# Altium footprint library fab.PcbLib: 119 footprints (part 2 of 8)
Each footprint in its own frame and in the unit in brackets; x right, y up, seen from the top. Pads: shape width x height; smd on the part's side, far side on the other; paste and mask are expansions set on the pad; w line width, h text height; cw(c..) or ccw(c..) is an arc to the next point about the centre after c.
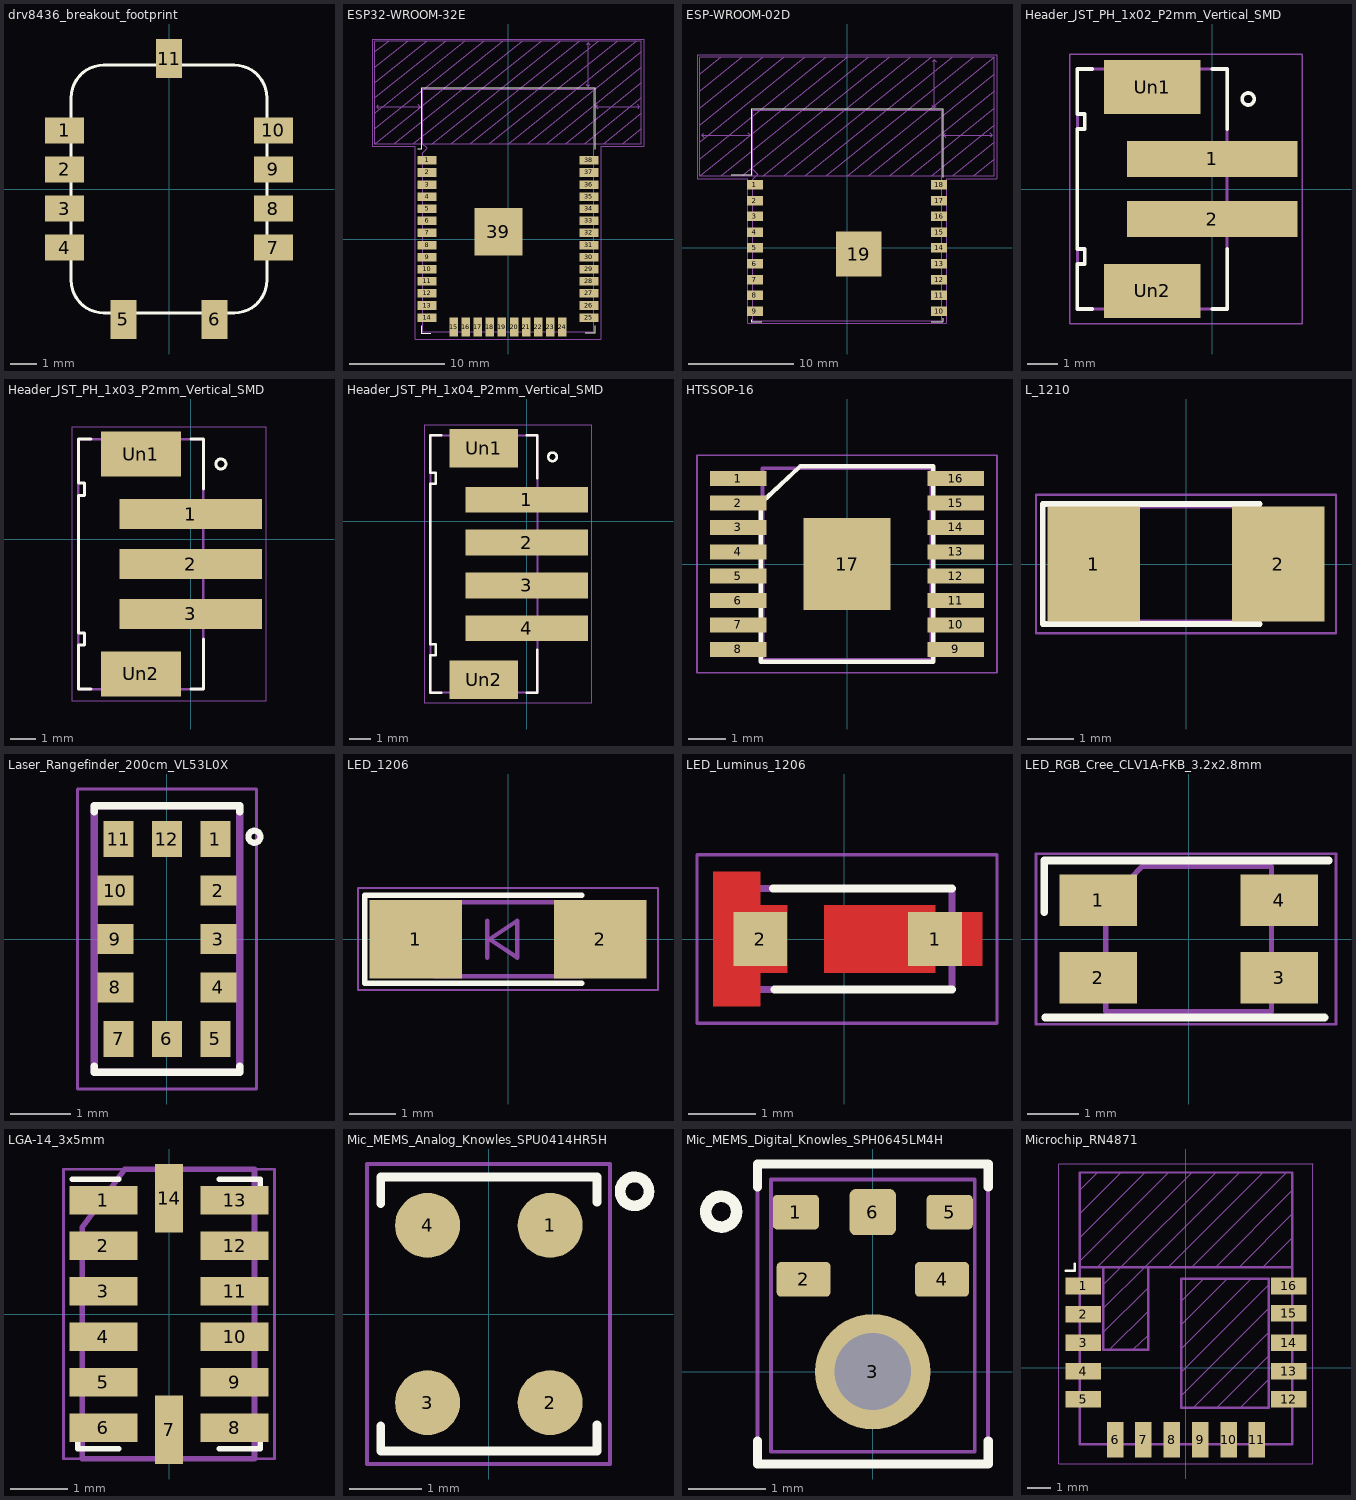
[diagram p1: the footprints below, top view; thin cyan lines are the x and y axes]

## drv8436_breakout_footprint [mm]
pads (11):
  rect 1.5x1 smd: 1(-4,2.25) 2(-4,0.75) 3(-4,-0.75) 4(-4,-2.25) 7(4,-2.25) 8(4,-0.75) 9(4,0.75) 10(4,2.25)
  rect 1x1.5 smd: 5(-1.75,-5) 6(1.75,-5) 11(0,5)
F.SilkS:
  lines w0.12: -3.75,-3.5 ccw(c-2.5,-3.5) -2.5,-4.75 2.5,-4.75 ccw(c2.5,-3.5) 3.75,-3.5 3.75,3.5 ccw(c2.5,3.5) 2.5,4.75 -2.5,4.75 ccw(c-2.5,3.5) -3.75,3.5 -3.75,-3.5

## ESP32-WROOM-32E [mm]
pads (39):
  rect 2x0.9 smd: 1(-8.5,8.255) 2(-8.5,6.985) 3(-8.5,5.715) 4(-8.5,4.445) 5(-8.5,3.175) 6(-8.5,1.905) 7(-8.5,0.635) 8(-8.5,-0.635) 9(-8.5,-1.905) 10(-8.5,-3.175) 11(-8.5,-4.445) 12(-8.5,-5.715) 13(-8.5,-6.985) 14(-8.5,-8.255) 25(8.5,-8.255) 26(8.5,-6.985) 27(8.5,-5.715) 28(8.5,-4.445) 29(8.5,-3.175) 30(8.5,-1.905) 31(8.5,-0.635) 32(8.5,0.635) 33(8.5,1.905) 34(8.5,3.175) 35(8.5,4.445) 36(8.5,5.715) 37(8.5,6.985) 38(8.5,8.255)
  rect 0.9x2 smd: 15(-5.715,-9.255) 16(-4.445,-9.255) 17(-3.175,-9.255) 18(-1.905,-9.255) 19(-0.635,-9.255) 20(0.635,-9.255) 21(1.905,-9.255) 22(3.175,-9.255) 23(4.445,-9.255) 24(5.715,-9.255)
  rect 5x5 smd: 39(-1,0.755)
F.SilkS:
  lines w0.12: -9.5,9.445 -9.12,9.445 -9.12,15.865 9.12,15.865 9.12,9.445 ; -9.12,-9.1 -9.12,-9.88 -8.12,-9.88 ; 8.12,-9.88 9.12,-9.88 9.12,-9.1
Dwgs.User:
  lines w0.1: -14,11.585 -2.525,20.75 ; -14,13.2 -4.525,20.75 ; -14,14.815 -6.525,20.75 ; -14,16.43 -8.525,20.75 ; -14,18.045 -10.525,20.75 ; -14,19.66 -12.525,20.75 ; -12,9.97 1.475,20.75 ; -10,9.97 3.475,20.75 ; -8,9.97 5.475,20.75 ; -6,9.97 7.475,20.75 ; -4,9.97 9.475,20.75 ; -2,9.97 11.475,20.75 ; -0.525,20.75 -14,9.97 ; 0,9.97 13.475,20.75 ; 2,9.97 14,19.66 ; 4,9.97 14,18.045 ; 6,9.97 14,16.43 ; 8,9.97 14,14.815 ; 10,9.97 14,13.2 ; 12,9.97 14,11.585 ; -14,9.97 14,9.97 14,20.75 -14,20.75 -14,9.97
F.CrtYd:
  lines w0.05: -14.25,9.72 -9.75,9.72 -9.75,-10.5 9.75,-10.5 9.75,9.72 14.25,9.72 14.25,21 -14.25,21 -14.25,9.72
F.Fab:
  lines w0.1: -9,-9.76 -9,9.02 -8.5,9.52 -9,10.02 -9,15.745 9,15.745 9,-9.76 -9,-9.76
  text "%R" at -0.393,-0.294 h1
Cmts.User:
  lines w0.1: -13.6,13.675 -13.8,13.875 ; -13.6,14.075 -13.8,13.875 ; -9.4,13.675 -9.2,13.875 ; -9.4,14.075 -9.2,13.875 ; 8.2,16.2 8.4,16 ; 8.2,20.4 8.4,20.6 ; 8.6,16.2 8.4,16 ; 8.6,20.4 8.4,20.6 ; 9.4,13.675 9.2,13.875 ; 9.4,14.075 9.2,13.875 ; 13.6,13.675 13.8,13.875 ; 13.6,14.075 13.8,13.875 ; -13.8,13.875 -9.2,13.875 ; 8.4,16 8.4,20.6 ; 9.2,13.875 13.8,13.875
  text "KEEP-OUT ZONE" at -1.89,18.715 h1
  text "Antenna" at -0.943,12.716 h1
  text "5 mm" at 11.454,14.234 h0.5
  text "5 mm" at -11.546,14.234 h0.5
  text "5 mm" at 7.941,18.729 h0.5

## ESP-WROOM-02D [mm]
pads (19):
  rect 1.5x0.9 smd: 1(-8.75,6) 2(-8.75,4.5) 3(-8.75,3) 4(-8.75,1.5) 5(-8.75,0) 6(-8.75,-1.5) 7(-8.75,-3) 8(-8.75,-4.5) 9(-8.75,-6) 10(8.75,-6) 11(8.75,-4.5) 12(8.75,-3) 13(8.75,-1.5) 14(8.75,0) 15(8.75,1.5) 16(8.75,3) 17(8.75,4.5) 18(8.75,6)
  rect 4.3x4.3 smd: 19(1.12,-0.58)
F.SilkS:
  lines w0.1: -11,6.9 -9.12,6.9 -9.12,13.22 9.12,13.22 9.12,6.7 ; -9.12,-6.8 -9.12,-7.02 -8.1,-7.02 ; 8,-7.02 9.12,-7.02 ; 9.12,-7 9.12,-6.7
Dwgs.User:
  lines w0.1: -14,6.795 0,18.1 ; -14,8.41 -2,18.1 ; -14,10.025 -4,18.1 ; -14,11.64 -6,18.1 ; -14,13.255 -8,18.1 ; -14,14.87 -10,18.1 ; -14,16.485 -12,18.1 ; -12,6.795 2,18.1 ; -10,6.795 4,18.1 ; -9,6.8 -9,13.1 9,13.1 9,6.78 ; -8,6.795 6,18.1 ; -6,6.795 8,18.1 ; -4,6.795 10,18.1 ; -2,6.795 12,18.1 ; 0,6.795 14,18.1 ; 2,6.795 14,16.485 ; 4,6.795 14,14.87 ; 6,6.795 14,13.255 ; 8,6.795 14,11.64 ; 10,6.795 14,10.025 ; 12,6.795 14,8.41 ; 14,18.1 14,6.8 -14,6.8 -14,18.1 14,18.1
F.CrtYd:
  lines w0.05: -14.25,6.55 -14.25,18.35 14.25,18.35 14.25,6.55 9.41,6.55 9.41,-7.15 -9.41,-7.15 -9.41,6.55 -14.25,6.55
F.Fab:
  lines w0.1: -9,-6.9 9,-6.9 9,13.1 -9,13.1 -9,7.5 -8.5,7 -9,6.5 -9,-6.9
  text "%R" at -0.393,-0.294 h1
Cmts.User:
  lines w0.1: -13.6,10.5 -13.8,10.7 ; -13.6,10.9 -13.8,10.7 ; -9.4,10.5 -9.2,10.7 ; -9.4,10.9 -9.2,10.7 ; 8.1,13.5 8.3,13.3 ; 8.1,17.7 8.3,17.9 ; 8.5,13.5 8.3,13.3 ; 8.5,17.7 8.3,17.9 ; 9.4,10.5 9.2,10.7 ; 9.4,10.9 9.2,10.7 ; 13.6,10.5 13.8,10.7 ; 13.6,10.9 13.8,10.7 ; -13.8,10.7 -9.2,10.7 ; 8.3,13.3 8.3,17.9 ; 9.2,10.7 13.8,10.7
  text "5 mm" at 7.941,15.554 h0.5
  text "5 mm" at -11.546,11.059 h0.5
  text "5 mm" at 11.454,11.059 h0.5
  text "Antenna" at -0.943,9.716 h1
  text "KEEP-OUT ZONE" at -1.89,15.715 h1

## Header_JST_PH_1x02_P2mm_Vertical_SMD [mm]
pads (4):
  rect 5.7x1.2 smd: 1(0,1) 2(0,-1)
  rect 3.2x1.8 smd: Un1(-2,3.4) Un2(-2,-3.4)
F.SilkS:
  circle w0.12: c1.2,3 r0.2
  lines w0.12: -4,-4 -4.5,-4 -4.5,-2.5 -4.25,-2.5 -4.25,-2 -4.5,-2 -4.5,2 -4.25,2 -4.25,2.5 -4.5,2.5 -4.5,4 -4,4 ; 0,-4 0.5,-4 0.5,-2 ; 0,4 0.5,4 0.5,2
F.CrtYd:
  lines w0.05: -4.75,-4.5 3,-4.5 3,4.5 -4.75,4.5 -4.75,-4.5
F.Fab:
  lines w0.1: -4.5,-4 0.5,-4 0.5,4 -4.5,4 -4.5,-4

## Header_JST_PH_1x03_P2mm_Vertical_SMD [mm]
pads (5):
  rect 5.7x1.2 smd: 1(0,1) 2(0,-1) 3(0,-3)
  rect 3.2x1.8 smd: Un1(-2,3.4) Un2(-2,-5.4)
F.SilkS:
  circle w0.12: c1.2,3 r0.2
  lines w0.12: -4,-6 -4.5,-6 -4.5,-4.25 -4.25,-4.25 -4.25,-3.75 -4.5,-3.75 -4.5,1.75 -4.25,1.75 -4.25,2.25 -4.5,2.25 -4.5,4 -4,4 ; 0,-6 0.5,-6 0.5,-4 ; 0,4 0.5,4 0.5,2
F.CrtYd:
  lines w0.05: -4.75,-6.5 3,-6.5 3,4.5 -4.75,4.5 -4.75,-6.5
F.Fab:
  lines w0.1: -4.5,-6 0.5,-6 0.5,4 -4.5,4 -4.5,-6

## Header_JST_PH_1x04_P2mm_Vertical_SMD [mm]
pads (6):
  rect 5.7x1.2 smd: 1(0,1) 2(0,-1) 3(0,-3) 4(0,-5)
  rect 3.2x1.8 smd: Un1(-2,3.4) Un2(-2,-7.4)
F.SilkS:
  circle w0.12: c1.2,3 r0.2
  lines w0.12: -4,-8 -4.5,-8 -4.5,-6.25 -4.25,-6.25 -4.25,-5.75 -4.5,-5.75 -4.5,1.75 -4.25,1.75 -4.25,2.25 -4.5,2.25 -4.5,4 -4,4 ; 0,-8 0.5,-8 0.5,-6 ; 0,4 0.5,4 0.5,2
F.CrtYd:
  lines w0.05: -4.75,-8.5 3,-8.5 3,4.5 -4.75,4.5 -4.75,-8.5
F.Fab:
  lines w0.1: -4.5,-8 0.5,-8 0.5,4 -4.5,4 -4.5,-8

## HTSSOP-16 [mm]
pads (17):
  rect 1.5x0.4 smd: 1(-2.9,2.275) 2(-2.9,1.625) 3(-2.9,0.975) 4(-2.9,0.325) 5(-2.9,-0.325) 6(-2.9,-0.975) 7(-2.9,-1.625) 8(-2.9,-2.275) 9(2.9,-2.275) 10(2.9,-1.625) 11(2.9,-0.975) 12(2.9,-0.325) 13(2.9,0.325) 14(2.9,0.975) 15(2.9,1.625) 16(2.9,2.275)
  rect 2.31x2.46 smd: 17(0,0)
F.SilkS:
  lines w0.12: -2.3,-2.6 -2.3,1.625 -1.25,2.6 2.3,2.6 2.3,-2.6 -2.3,-2.6
F.CrtYd:
  lines w0.05: -4,-2.9 -4,2.9 4,2.9 4,-2.9 -4,-2.9
F.Fab:
  lines w0.1: -2.25,-2.55 -2.25,2.55 2.25,2.55 2.25,-2.55 -2.25,-2.55

## L_1210 [mm]
pads (2):
  rect 2x2.5 smd: 1(-2,0) 2(2,0)
F.SilkS:
  lines w0.12: 1.6,-1.3 -3.1,-1.3 -3.1,1.3 1.6,1.3
F.CrtYd:
  lines w0.05: -3.25,-1.5 3.25,-1.5 3.25,1.5 -3.25,1.5 -3.25,-1.5
F.Fab:
  lines w0.1: -1.6,-1.25 1.6,-1.25 1.6,1.25 -1.6,1.25 -1.6,-1.25

## Laser_Rangefinder_200cm_VL53L0X [mm]
pads (12):
  rect 0.5x0.6 smd: 1(0.8,1.65) 5(0.8,-1.65) 6(0,-1.65) 7(-0.8,-1.65) 11(-0.8,1.65) 12(0,1.65)
  rect 0.6x0.5 smd: 2(0.85,0.8) 3(0.85,0) 4(0.85,-0.8) 8(-0.85,-0.8) 9(-0.85,0) 10(-0.85,0.8)
F.SilkS:
  circle w0.1: c1.444,1.689 r0.1
  lines w0.127: -1.2,-2.1 -1.2,-2.2 1.2,-2.2 1.2,-2.1 ; -1.2,2.1 -1.2,2.2 1.2,2.2 1.2,2.1
F.CrtYd:
  lines w0.05: -1.477,-2.477 1.477,-2.477 1.477,2.477 -1.477,2.477 -1.477,-2.477
F.Fab:
  lines w0.127: -1.2,-2.2 -1.2,2.2 1.2,2.2 1.2,-2.2 -1.2,-2.2

## LED_1206 [mm]
pads (2):
  rect 2x1.7 smd: 1(-2,0) 2(2,0)
F.SilkS:
  lines w0.12: 1.6,-0.95 -3.1,-0.95 -3.1,0.95 1.6,0.95
F.CrtYd:
  lines w0.05: -3.25,-1.1 3.25,-1.1 3.25,1.11 -3.25,1.11 -3.25,-1.1
F.Fab:
  lines w0.1: -0.45,-0.4 -0.45,0.4 ; -1.6,-0.8 1.6,-0.8 1.6,0.8 -1.6,0.8 -1.6,-0.8 ; -0.4,0 0.2,-0.4 0.2,0.4 -0.4,0

## LED_Luminus_1206 [mm]
pads (2):
  rect 0.8x0.8 smd: 1(1.35,0) 2(-1.25,0)
F.Cu:
  region: -0.85,-0.5 -1.25,-0.5 -1.25,0.5 -0.85,0.5
  region: -1.25,-1 -1.95,-1 -1.95,1 -1.25,1
  region: 2.05,-0.4 1.35,-0.4 1.35,0.4 2.05,0.4
  region: 1.35,-0.5 -0.3,-0.5 -0.3,0.5 1.35,0.5
F.SilkS:
  lines w0.12: -1.06,0.75 1.6,0.75 ; -1.04,-0.75 1.6,-0.75
F.Paste:
  region: -0.85,-0.5 -1.25,-0.5 -1.25,0.5 -0.85,0.5
  region: -1.25,-1 -1.95,-1 -1.95,1 -1.25,1
  region: 2.05,-0.4 1.35,-0.4 1.35,0.4 2.05,0.4
  region: 1.35,-0.5 -0.3,-0.5 -0.3,0.5 1.35,0.5
F.Mask:
  region: -0.85,-0.5 -1.25,-0.5 -1.25,0.5 -0.85,0.5
  region: -1.25,-1 -1.95,-1 -1.95,1 -1.25,1
  region: 2.05,-0.4 1.35,-0.4 1.35,0.4 2.05,0.4
  region: 1.35,-0.5 -0.3,-0.5 -0.3,0.5 1.35,0.5
F.CrtYd:
  lines w0.05: -2.19,-1.25 -2.19,1.25 2.27,1.25 2.27,-1.25 -2.19,-1.25
F.Fab:
  lines w0.1: -1.5,-0.75 -1.5,0.75 1.6,0.75 1.6,-0.75 -1.5,-0.75

## LED_RGB_Cree_CLV1A-FKB_3.2x2.8mm [mm]
pads (4):
  rect 1.5x1 smd: 1(-1.75,0.75) 2(-1.75,-0.75) 3(1.75,-0.75) 4(1.75,0.75)
F.SilkS:
  lines w0.15: -2.79,0.52 -2.79,1.52 2.71,1.52 ; -2.77,-1.52 2.63,-1.52
F.CrtYd:
  lines w0.05: -2.95,-1.65 -2.95,1.65 2.85,1.65 2.85,-1.65 -2.95,-1.65
F.Fab:
  lines w0.1: -1.6,-1.4 -1.6,0.675 -0.9,1.4 1.6,1.4 1.6,-1.4 -1.6,-1.4
  text "%R" at -0.393,2.206 h1

## LGA-14_3x5mm [mm]
pads (14):
  rect 1.2x0.5 smd: 1(-1.15,2) 2(-1.15,1.2) 3(-1.15,0.4) 4(-1.15,-0.4) 5(-1.15,-1.2) 6(-1.15,-2) 8(1.15,-2) 9(1.15,-1.2) 10(1.15,-0.4) 11(1.15,0.4) 12(1.15,1.2) 13(1.15,2)
  rect 0.5x1.2 smd: 7(0,-2.032) 14(0,2.032)
F.SilkS:
  lines w0.1: -1.7,2.366 -0.88,2.366 ; -1.6,-2.146 -1.6,-2.366 -0.88,-2.366 ; 0.88,-2.366 1.6,-2.366 1.6,-2.146 ; 0.88,2.366 1.6,2.366 1.6,2.146
F.CrtYd:
  lines w0.05: -1.85,-2.54 1.85,-2.54 1.85,2.54 -1.85,2.54 -1.85,-2.54
F.Fab:
  lines w0.1: -1.524,-2.54 -1.524,1.524 -0.774,2.54 ; -1.5,-2.54 1.5,-2.54 1.5,2.54 -0.75,2.54
  text "%R" at -0.197,-0.147 h0.5

## Mic_MEMS_Analog_Knowles_SPU0414HR5H [mm]
pads (4):
  round 0.9 smd: 1(0.85,1.23) 2(0.85,-1.23) 3(-0.85,-1.23) 4(-0.85,1.23)
F.SilkS:
  circle w0.15: c2.02,1.7 r0.2
  lines w0.12: -1.5,-1.55 -1.5,-1.9 1.5,-1.9 1.5,-1.54 ; -1.5,1.53 -1.5,1.9 1.5,1.9 1.5,1.55
F.Fab:
  lines w0.05: -1.69,-2.08 1.68,-2.08 1.68,2.08 -1.69,2.08 -1.69,-2.08

## Mic_MEMS_Digital_Knowles_SPH0645LM4H [mm]
pads (6):
  rrect25% 0.6x0.45 smd: 1(-1,2.074) 5(1,2.074)
  rrect25% 0.7x0.45 smd: 2(-0.9,1.2) 4(0.9,1.2)
  round 1.5 hole 1: 3(0,0)
  rrect25% 0.6x0.6 smd: 6(0,2.074)
F.SilkS:
  circle w0.15: c-1.97,2.08 r0.2
  lines w0.12: -1.5,-0.9 -1.5,-1.2 1.5,-1.2 1.5,-0.9 ; -1.5,2.4 -1.5,2.7 1.5,2.7 1.5,2.4
F.CrtYd:
  lines w0.05: -1.5,-1.2 1.5,-1.2 1.5,2.7 -1.5,2.7 -1.5,-1.2
F.Fab:
  lines w0.05: -1.325,-1.04 -1.325,2.5 1.325,2.5 1.325,-1.04 -1.325,-1.04

## Microchip_RN4871 [mm]
pads (16):
  rect 1.5x0.7 smd: 1(-4.35,3.45) 2(-4.35,2.25) 3(-4.35,1.05) 4(-4.35,-0.15) 5(-4.35,-1.35) 12(4.35,-1.35) 13(4.35,-0.15) 14(4.35,1.05) 15(4.35,2.3) 16(4.35,3.45)
  rect 0.7x1.5 smd: 6(-3,-3.05) 7(-1.8,-3.05) 8(-0.6,-3.05) 9(0.6,-3.05) 10(1.8,-3.05) 11(3,-3.05)
F.SilkS:
  lines w0.1: -5.1,4.1 -4.7,4.1 -4.7,4.4
Dwgs.User:
  lines w0.05: -4.5,4.5 -0.75,8.25 ; -4.5,5.5 -1.75,8.25 ; -4.5,6.5 -2.75,8.25 ; -4.5,7.5 -3.75,8.25 ; -3.75,4.25 0.25,8.25 ; -3.5,1.5 -1.6,3.375 ; -3.5,2.5 -1.75,4.25 2.25,8.25 ; -3.5,3.5 -2.75,4.25 1.25,8.25 ; -3.25,0.75 -1.6,2.375 ; -2.25,0.75 -1.6,1.375 ; -0.75,4.25 3.25,8.25 ; -0.2,-1.2 3.5,2.5 ; -0.2,-0.2 3.5,3.5 ; -0.2,0.8 2.75,3.75 ; -0.2,1.8 1.75,3.75 ; -0.2,2.8 0.75,3.75 ; 0.25,4.25 4.25,8.25 ; 0.3,-1.7 3.5,1.5 ; 1.25,4.25 4.5,7.5 ; 1.3,-1.7 3.5,0.5 ; 2.25,4.25 4.5,6.5 ; 2.3,-1.7 3.5,-0.5 ; 3.25,4.25 4.5,5.5
  lines w0.1: -4.5,4.25 4.5,4.25 4.5,8.25 -4.5,8.25 -4.5,4.25 ; -3.5,0.75 -1.6,0.75 -1.6,4.25 -3.5,4.25 -3.5,0.75 ; -0.2,-1.7 -0.2,3.75 3.5,3.75 3.5,-1.7 -0.2,-1.7
F.CrtYd:
  lines w0.05: 5.36,8.61 5.36,-4.08 -5.38,-4.08 -5.38,8.61 5.38,8.61
F.Fab:
  lines w0.1: -4.5,8.25 -4.5,-3.25 4.5,-3.25 4.5,8.25
  text "%R" at -0.393,2.206 h1
Cmts.User:
  text "On any layer" at -0.393,5.604 h0.25
  text "No Metal, No Traces, Components" at -1.013,6.105 h0.25
  text "KEEP-OUT ZONE" at 1.896,0.352 h0.25
  text "KEEP-OUT ZONE" at -2.504,2.027 h0.25
  text "KEEP-OUT ZONE" at -0.945,7.158 h0.5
